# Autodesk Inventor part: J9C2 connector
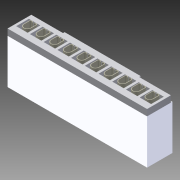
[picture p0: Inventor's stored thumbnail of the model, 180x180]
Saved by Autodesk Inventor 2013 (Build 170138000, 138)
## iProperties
Company: Autodesk Inc.
Created: 2005-12
Part Number: J9C2 connector
Document SubType Name: Modeling
Designer: Autodesk Inc.
Density: 1 g/cm^3
Mass: 0.594326 g
Surface Area: 11.2983 cm^2
Volume: 0.594326 cm^3
Material: Allgemein
Title: Personal Computer
Author: Autodesk Inc.
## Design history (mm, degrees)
sketch "Sketch1"
  geometry: L1 (0, 2.8)-(0, -2.8) reference; L2 (-15.4, 0)-(15.4, 0) reference; L3 (-11, 2)-(11, 2); L4 (11, 2)-(11, -2); L5 (11, -2)-(-11, -2); L6 (-11, -2)-(-11, 2)
  constraints: 8 end point, 2 parallel, 1 horizontal, 1 perpendicular, 2 other
  dimensions: "d0" = 22 distance of L3.start L3.end; "d1" = 4 distance of L5.end L3.start
extrude "Extrusion1" new body sketch "Sketch1" distance "d2" = 8; taper "d3" = 0 deg
sketch "Sketch2"
  geometry: L1 (11, 2)-(11, -2) reference; L2 (-15.4, 0)-(15.4, 0) reference; L3 (10.636, 1)-(8.836, 1); L4 (8.836, 1)-(8.836, -1); L5 (8.836, -1)-(10.636, -1); L6 (10.636, -1)-(10.636, 1)
  constraints: 8 end point, 2 parallel, 1 horizontal, 1 perpendicular, 1 other
  dimensions: "d4" = 2 distance of L5.end L3.start; "d5" = 1.8 distance of L3.start L3.end; "d6" = 0.36364 distance between parallel lines of L1 L6
extrude "Extrusion2" cut sketch "Sketch2" distance "d7" = 3; taper "d8" = 0 deg
pattern_linear "Rectangular Pattern1" dims "d11" = 2.16364
sketch "Sketch3"
  geometry: L1 (-11, 2)-(-6, 2); L2 (-6, 2)-(-6, 1.75); L3 (-6, 1.75)-(-11, 1.75); L4 (-11, 1.75)-(-11, 2); L5 (11, 2)-(6, 2); L6 (6, 2)-(6, 1.75); L7 (6, 1.75)-(11, 1.75); L8 (11, 1.75)-(11, 2)
  constraints: 16 end point, 4 parallel, 2 collinear, 2 horizontal, 2 perpendicular
  dimensions: "d12" = 5 distance of L2.end L3.end; "d13" = 0.25 distance of L1.end L2.end
extrude "Extrusion3" cut sketch "Sketch3" distance "d14" = 1; taper "d15" = 0 deg
sketch "Sketch4"
  geometry: L1 (0, -7)-(5, -7) reference; L2 (5, -7)-(4.8, -7); L3 (4.8, -7)-(4.8, -2); L4 (4.8, -2)-(5, -2); L5 (5, -2)-(5, -7); L6 (17, -7)-(17.2, -7); L7 (17.2, -7)-(17.2, -2); L8 (17.2, -2)-(17, -2); L9 (17, -2)-(17, -7); L10 (17, -2)-(17, -2.2); L11 (5, -2.2)-(5, -2); L12 (5, -2)-(17, -2); L13 (17, -2)-(17, -2.2); L14 (17, -2.2)-(5, -2.2); L15 (5, -2.2)-(5, -2)
  constraints: 28 end point, 7 parallel, 3 horizontal, 3 perpendicular, 2 equal length, 2 point on line
  dimensions: "d16" = 0.2 distance of L3.end L4.end; "d19" = 5 distance between parallel lines of L1 L4; "d20" = 0.2 distance between parallel lines of L12 L14 (= d16)
extrude "Extrusion4" cut sketch "Sketch4" distance "d21" = 0.1; taper "d22" = 0 deg
workplane "Work Plane1"
split "Split1"
sketch "Sketch5"
  geometry: L1 (12, 0)-(12, 5.8) reference; L2 (12, 5.8)-(0, 5.8) reference; L3 (0, 5.8)-(0, 0) reference; L4 (0, 0)-(12, 0) reference; L5 (0.5, 5.8)-(11.5, 5.8); L6 (11.5, 5.8)-(11.5, 0.5); L7 (11.5, 0.5)-(0.5, 0.5); L8 (0.5, 0.5)-(0.5, 5.8)
  constraints: 8 end point, 2 parallel, 1 horizontal, 1 perpendicular, 1 point on line
  dimensions: "d24" = 0.5 distance between parallel lines of L3 L8; "d25" = 0.5 distance between parallel lines of L1 L6 (= d24); "d26" = 0.5 distance between parallel lines of L4 L7 (= d24)
extrude "Extrusion5" cut sketch "Sketch5" distance "d27" = 0.2; taper "d28" = 0 deg
sketch "Sketch6"
  geometry: L1 (8.836, -1)-(10.636, -1) reference; L2 (10.636, 1)-(8.836, 1) reference; L3 (9.736, 1)-(9.736, -1); L4 (10.324, 0.578)-(10.324, -0.306); L5 (9.149, 0.578)-(9.149, -0.306); L6 (10.236, 0.566)-(10.236, -0.306); L7 (9.236, -0.306)-(9.236, 0.566); L8 (9.595, 0.588)-(9.675, 0.623); L9 (9.878, 0.588)-(9.798, 0.623); A1 r 0.279 centre (10.053, 0.509) between (10.324, 0.578) and (9.798, 0.623); A2 r 0.279 centre (9.42, 0.509) between (9.675, 0.623) and (9.149, 0.578); A3 r 0.587 centre (9.736, -0.306) between (9.149, -0.306) and (10.324, -0.306); A4 r 0.192 centre (10.053, 0.509) between (10.236, 0.566) and (9.878, 0.588); A5 r 0.5 centre (9.736, -0.306) between (9.236, -0.306) and (10.236, -0.306); A6 r 0.192 centre (9.42, 0.509) between (9.595, 0.588) and (9.236, 0.566)
  constraints: 14 end point, 12 point on circle, 6 centre point, 4 symmetric about line, 2 midpoint, 2 tangent, 1 parallel, 5 other
  dimensions: "d29" = 0.5 radius of A5
extrude "Extrusion6" join sketch "Sketch6" distance "d30" = 3.2; taper "d31" = 0 deg
pattern_linear "Rectangular Pattern2" dims "d34" = 2.146
body "Solid1"
other parameters: "d23" = 0
